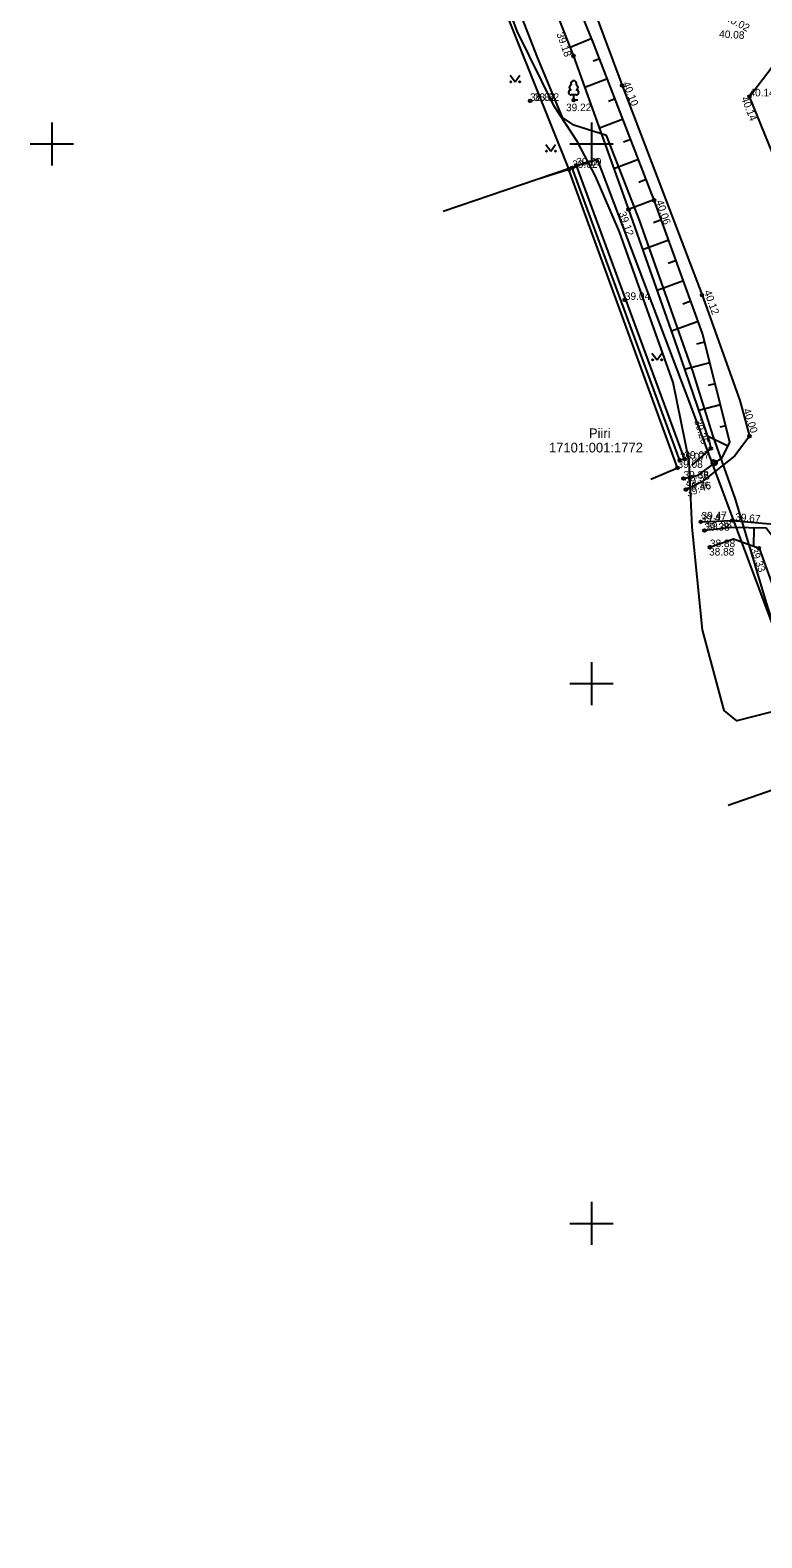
# Model space of a CAD drawing. Extents: x 627548 to 628052, y 6467984 to 6468802.
# Drawn here: x 627848 to 627915.8, y 6468120.9 to 6468260.5 of the extents above; entities that cross this region are included whole.
import ezdxf

# ---------------------------------------------------------------- set-up
doc = ezdxf.new("R2010")
doc.units = 0
for name, color, linetype in [('AED', 7, 'Continuous'), ('HALJASTUS', 7, 'Continuous'), ('KORGUS-EH2000', 7, 'Continuous'), ('MOOTKORG-EH2000', 7, 'Continuous'), ('MOOTMPUNKT', 7, 'Continuous'), ('PIIR', 7, 'Continuous'), ('POST', 7, 'Continuous'), ('PUU', 7, 'Continuous'), ('RELJEEF', 7, 'Continuous'), ('SITRASS', 7, 'Continuous'), ('TEE', 7, 'Continuous'), ('VORK', 7, 'Continuous')]:
    doc.layers.add(name, color=color, linetype=linetype)

msp = doc.modelspace()

# ---------------------------------------------------------------- linework, layer by layer
at = {"layer": 'AED'}
msp.add_lwpolyline([(627905.49, 6468218.96), (627907.97, 6468219.99), (627897.9, 6468247.65), (627894.88, 6468246.69)], dxfattribs=at)
at = {"layer": 'HALJASTUS'}
for p, q in [((627892.46, 6468256.37), (627892.93, 6468255.76)), ((627892.93, 6468255.76), (627893.37, 6468256.37)), ((627895.77, 6468249.95), (627896.23, 6468249.34)), ((627896.23, 6468249.34), (627896.68, 6468249.95)), ((627905.6, 6468230.61), (627906.07, 6468230)), ((627906.07, 6468230), (627906.51, 6468230.61))]:
    msp.add_line(p, q, dxfattribs=at)
for centre in [(627892.53, 6468255.76), (627893.35, 6468255.76), (627895.83, 6468249.34), (627896.66, 6468249.34), (627905.67, 6468230), (627906.5, 6468230)]:
    msp.add_circle(centre, 0.055, dxfattribs=at)
at = {"layer": 'KORGUS-EH2000'}
for centre in [(627898.34, 6468258.15), (627902.84, 6468255.42), (627898.35, 6468254.06), (627897.9, 6468247.65), (627905.81, 6468244.78), (627903.42, 6468243.92), (627910.24, 6468236), (627914.64, 6468222.92), (627911.05, 6468221.79), (627913.06, 6468215.12), (627915.52, 6468212.56)]:
    msp.add_circle(centre, 0.125, dxfattribs=at)
at = {"layer": 'MOOTMPUNKT'}
for centre in [(627914.63, 6468254.41), (627894.31, 6468253.99), (627898.22, 6468247.78), (627898.58, 6468248.01), (627903.09, 6468235.56), (627908.6, 6468220.84), (627907.97, 6468219.99), (627908.19, 6468220.69), (627908.53, 6468219), (627908.74, 6468217.99), (627910.11, 6468214.99), (627910.46, 6468214.18), (627910.97, 6468212.65)]:
    msp.add_circle(centre, 0.125, dxfattribs=at)
at = {"layer": 'PIIR'}
for p, q in [((627869.12, 6468319.4), (627897.87, 6468247.69)), ((627897.87, 6468247.69), (627886.25, 6468243.73)), ((627900.56, 6468248.6), (627897.87, 6468247.69)), ((627909.15, 6468225.92), (627900.56, 6468248.6)), ((627921.83, 6468191.92), (627909.15, 6468225.92)), ((627912.65, 6468188.74), (627921.83, 6468191.92))]:
    msp.add_line(p, q, dxfattribs=at)
at = {"layer": 'POST'}
msp.add_line((627911.2, 6468220.28), (627911.55, 6468220.64), dxfattribs=at)
msp.add_circle((627911.37, 6468220.46), 0.25, dxfattribs=at)
for radius, start, end in [(0.225, 224.8541, 45.0356), (0.2, 224.8427, 45.047), (0.175, 224.8281, 45.0616), (0.15, 224.8087, 45.081), (0.125, 224.7814, 45.1083), (0.1, 224.7406, 45.1491), (0.075, 224.6725, 45.2172), (0.05, 224.5363, 45.3534), (0.025, 224.1278, 45.7619)]:
    msp.add_arc((627911.37, 6468220.46), radius, start, end, dxfattribs=at)
at = {"layer": 'PUU'}
for p, q in [((627898.59, 6468254.54), (627898.11, 6468254.54)), ((627898.35, 6468254.06), (627898.35, 6468254.54)), ((627898.73, 6468254.06), (627898.35, 6468254.06))]:
    msp.add_line(p, q, dxfattribs=at)
for points in [[(627908.19, 6468220.69), (627898.22, 6468247.78)], [(627898.58, 6468248.01), (627908.6, 6468220.84)]]:
    msp.add_lwpolyline(points, dxfattribs=at)
for centre, radius, start, end in [((627898.35, 6468255.58), 0.277, 332.5799, 207.4201), ((627898.11, 6468254.78), 0.238, 90.0016, 269.3953), ((627898.18, 6468255.24), 0.233, 109.0217, 253.1415), ((627898.52, 6468255.24), 0.233, 286.8508, 70.9859), ((627898.59, 6468254.78), 0.238, 270.6047, 89.9984)]:
    msp.add_arc(centre, radius, start, end, dxfattribs=at)
at = {"layer": 'RELJEEF'}
for p, q in [((627900.03, 6468259.76), (627898.03, 6468258.95)), ((627900.76, 6468257.9), (627900.15, 6468257.66)), ((627901.48, 6468256.03), (627899.39, 6468255.23)), ((627902.2, 6468254.17), (627901.56, 6468253.92)), ((627902.92, 6468252.3), (627900.73, 6468251.46)), ((627903.63, 6468250.43), (627902.96, 6468250.18)), ((627904.35, 6468248.57), (627902.08, 6468247.69)), ((627905.07, 6468246.7), (627904.37, 6468246.43)), ((627905.79, 6468244.84), (627903.42, 6468243.92)), ((627906.47, 6468242.96), (627905.75, 6468242.69)), ((627907.15, 6468241.08), (627904.74, 6468240.2)), ((627907.84, 6468239.19), (627907.11, 6468238.93)), ((627908.52, 6468237.31), (627906.07, 6468236.43)), ((627909.2, 6468235.43), (627908.46, 6468235.17)), ((627909.88, 6468233.55), (627907.4, 6468232.66)), ((627910.48, 6468231.65), (627909.73, 6468231.46)), ((627910.97, 6468229.71), (627908.63, 6468229.12)), ((627911.47, 6468227.77), (627910.81, 6468227.61)), ((627911.96, 6468225.83), (627909.94, 6468225.32)), ((627912.45, 6468223.89), (627911.89, 6468223.75)), ((627912.64, 6468221.99), (627910.76, 6468222.93)), ((627911.44, 6468220.46), (627911.22, 6468220.77)), ((627915.05, 6468214.43), (627915.01, 6468212.74))]:
    msp.add_line(p, q, dxfattribs=at)
for points in [[(627908.53, 6468219), (627909.81, 6468219.3), (627912.11, 6468220.93), (627912.83, 6468222.37), (627910.29, 6468232.44), (627905.81, 6468244.78), (627900.2, 6468259.35), (627892.99, 6468277.05), (627890.57, 6468283.16), (627885.62, 6468283.82)], [(627885.57, 6468283.7), (627886.2, 6468283.02), (627889.41, 6468282.35), (627891.21, 6468276.22), (627898.34, 6468258.15), (627903.42, 6468243.92), (627907.95, 6468231.1), (627910.91, 6468222.47), (627911.05, 6468221.79), (627909.27, 6468220.22)], [(627978.29, 6468008.88), (627983.46, 6468013.68), (627984.21, 6468021.02), (627979.57, 6468037.02), (627973.98, 6468054.36), (627968.22, 6468070.61), (627961.47, 6468089.43), (627957.41, 6468099.78), (627954.7, 6468099.95), (627954.6, 6468100.77), (627956.68, 6468103.29), (627952.11, 6468117.09), (627946.48, 6468133.26), (627941.38, 6468147.78), (627936.22, 6468162.71), (627931.41, 6468176.01), (627926.77, 6468189.07), (627921.45, 6468202.33), (627917.81, 6468212.3), (627916.17, 6468214.41), (627912.96, 6468214.48), (627910.46, 6468214.18)], [(627910.97, 6468212.65), (627913.16, 6468213.42), (627915.52, 6468212.56), (627919.56, 6468201.38), (627924.57, 6468188.42), (627929.21, 6468175.58), (627934.91, 6468161.37), (627939.16, 6468147.56), (627944.58, 6468131.87), (627949.81, 6468116.9), (627954.8, 6468102.83), (627953.15, 6468101.41), (627953.98, 6468098.42), (627956.49, 6468098.12), (627959.58, 6468088.97), (627966.66, 6468069), (627971.68, 6468054.44), (627977.14, 6468035.88), (627981.19, 6468020.39), (627981.64, 6468013.54), (627978.21, 6468009.48)]]:
    msp.add_lwpolyline(points, dxfattribs=at)
at = {"layer": 'SITRASS'}
for points in [[(627921.09, 6468198.49), (627913.45, 6468196.56), (627912.3, 6468197.52), (627910.28, 6468205), (627909.34, 6468214.5), (627909.05, 6468220.62), (627907.57, 6468227.9), (627902.6, 6468241.86), (627900.36, 6468247.03), (627898.69, 6468250.2), (627896.53, 6468253.5), (627893.11, 6468260.45), (627888.84, 6468271.87)], [(627947.22, 6468119.58), (627940.94, 6468137.54), (627936.2, 6468151.11), (627931.36, 6468165.19), (627924.48, 6468184.01), (627921.14, 6468194.07), (627919.52, 6468197.09), (627916.21, 6468207.5), (627913.33, 6468217.08), (627911.26, 6468222.94), (627909.42, 6468228.85), (627904.46, 6468242.93), (627901.38, 6468250.77), (627898.37, 6468251.73), (627897.32, 6468252.46), (627895.04, 6468257.95), (627892.76, 6468263.75)]]:
    msp.add_lwpolyline(points, dxfattribs=at)
at = {"layer": 'TEE'}
for points in [[(627876.96, 6468285.02), (627874.35, 6468284.04), (627874.97, 6468280.92), (627876.21, 6468280.62), (627885.51, 6468284.03), (627891.07, 6468284.57), (627891.69, 6468283.86), (627895.62, 6468274.65), (627899.29, 6468264.96), (627902.84, 6468255.42), (627906.5, 6468245.88), (627910.24, 6468236), (627913.74, 6468226.22), (627914.64, 6468222.92), (627913.27, 6468221.1), (627910.19, 6468218.68), (627908.74, 6468217.99)], [(627929.71, 6468231.07), (627927.01, 6468230.5), (627923.67, 6468230.75), (627919.46, 6468241.82), (627916.75, 6468249.25), (627914.63, 6468254.41), (627916.63, 6468257.01), (627918.69, 6468258.4)], [(627910.11, 6468214.99), (627913.06, 6468215.12), (627917.93, 6468214.67), (627920.82, 6468207.04), (627924.55, 6468197.42), (627928.06, 6468187.89), (627931.44, 6468178.36), (627934.78, 6468168.69), (627938.38, 6468158.82), (627941.8, 6468149.3), (627945.3, 6468139.65), (627948.73, 6468130.07), (627952.16, 6468120.49)]]:
    msp.add_lwpolyline(points, dxfattribs=at)
at = {"layer": 'VORK'}
for p, q in [((627850, 6468252), (627850, 6468248)), ((627900, 6468252), (627900, 6468248)), ((627848, 6468250), (627852, 6468250)), ((627898, 6468250), (627902, 6468250)), ((627900, 6468202), (627900, 6468198)), ((627898, 6468200), (627902, 6468200)), ((627900, 6468152), (627900, 6468148)), ((627898, 6468150), (627902, 6468150))]:
    msp.add_line(p, q, dxfattribs=at)

# ---------------------------------------------------------------- texts
at = {"layer": 'KORGUS-EH2000'}
for s, rotation, p in [('40.02', 332.2395, (627912.35, 6468261.47)), (' 39.18', 289.6362, (627896.66, 6468260.45)), (' 40.08', 356.7887, (627911.55, 6468259.87)), (' 40.10', 290.9896, (627902.79, 6468255.87)), ('40.14', 291.8306, (627913.85, 6468254.23)), (' 40.06', 288.481, (627905.88, 6468244.93)), (' 39.12', 289.4746, (627902.42, 6468243.85)), (' 40.12', 289.7154, (627910.32, 6468236.56)), (' 40.00', 288.2137, (627913.95, 6468225.62)), (' 39.25', 287.0656, (627909.43, 6468224.61)), ('39.38', 17.1922, (627908.77, 6468218.29)), ('39.46', 21.3917, (627908.94, 6468217.28)), ('39.47', 1.2886, (627910.2, 6468215.2)), (' 39.67', 354.795, (627913.03, 6468215.14)), ('39.38', 5.2118, (627910.68, 6468214.2)), (' 39.33', 289.8571, (627914.62, 6468212.7))]:
    msp.add_text(s, height=0.7, rotation=rotation, dxfattribs=at).set_placement(p)
for s, p in [('38.82', (627894.66, 6468253.99)), (' 39.22', (627897.38, 6468253.04)), ('38.88', (627910.89, 6468211.87))]:
    msp.add_text(s, height=0.7, dxfattribs=at).set_placement(p)
at = {"layer": 'MOOTKORG-EH2000'}
for s, p in [('38.82', (627894.31, 6468253.99)), ('40.14', (627914.63, 6468254.41)), ('39.02', (627898.22, 6468247.78)), ('39.09', (627898.58, 6468248.01)), ('39.04', (627903.09, 6468235.56)), ('39.07', (627908.19, 6468220.69)), ('39.07', (627908.6, 6468220.84)), ('39.08', (627907.97, 6468219.99)), ('39.38', (627908.53, 6468219)), ('39.46', (627908.74, 6468217.99)), ('39.47', (627910.11, 6468214.99)), ('39.38', (627910.46, 6468214.18)), ('38.88', (627910.97, 6468212.65))]:
    msp.add_text(s, height=0.7, dxfattribs=at).set_placement(p)
at = {"layer": 'PIIR'}
for s, p in [('Piiri', (627899.76, 6468222.75)), ('17101:001:1772', (627896.06, 6468221.42))]:
    msp.add_text(s, height=0.9, dxfattribs=at).set_placement(p)

doc.saveas('drawing.dxf')
